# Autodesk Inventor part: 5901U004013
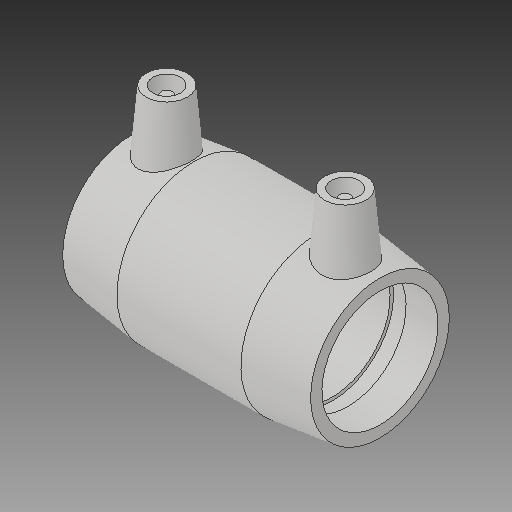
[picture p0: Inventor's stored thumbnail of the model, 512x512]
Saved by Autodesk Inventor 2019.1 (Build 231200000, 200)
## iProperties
Created: 2017-06
Part Number: 5901U004013
Material: Generic
Description: PLASSON CTS COUPLER 1 1/4''
Document SubType Name: Modeling
Designer: KIM
Mass: 72.9589 g
Surface Area: 285.531 cm^2
Volume: 72.9589 cm^3
Density: 1 g/cm^3
Appearance: Default
Author: KIM
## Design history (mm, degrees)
derived "5901U.ipt"
feature "Solid1::5901U.ipt"
tag "TaggingFeature1"
body "Solid1"
other parameters: "d0" = 89.916, "d1" = 42.1, "d2" = 55.88, "d3" = 43.434, "d4" = 22.479, "d5" = 50.292, "d6" = 33.68, "d7" = 42.1, "d8" = 168 deg, "d10" = 17.3736, "d11" = 5.7912, "d29" = 46.99, "d30" = 15, "d31" = 32.36976, "d34" = 5 deg, "d41" = 4, "d42" = 14, "d43" = 0, "d48" = 3, "d49" = 0, "d_" = 42.1, "L_" = 89.916, "L_1" = 43.434, "D_" = 55.88, "A_" = 46.99, "d_2" = 12
